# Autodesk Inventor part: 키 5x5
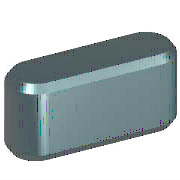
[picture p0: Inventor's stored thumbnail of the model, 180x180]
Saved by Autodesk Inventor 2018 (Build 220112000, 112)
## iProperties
IsCustomPart: 1
Created: 2012-02
Part Number: 키 5x5
Material: 강철, 연강
Description: 키 및 해당 키홈
Document SubType Name: Modeling
Standard: KS B 1311
Designer: mduedu
Standards Organization: KS
Language: ko-KR
Size Designation: 5 x 5 x 12
Categories: <MemberInstance><Categories><Category DisplayName="샤프트 부품" InternalName="7f7aeb1f-a693-4053-b835-cee3144e0d98" Mnemonic="SHFT"><Category DisplayName="키" Interna
Density: 1 g/cm^3
Appearance: 노란색
Author: mduedu
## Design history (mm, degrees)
workplane "Work Plane1"
workplane "Work Plane2"
sketch "스케치1"
  geometry: L1 (2.5, 2.5)-(9.5, 2.5); L2 (9.5, -2.5)-(2.5, -2.5); L3 (0, 9.4)-(0, -7.4) reference; L4 (-5, 0)-(30, 0) reference; L5 (12, 0)-(12, 7); A1 r 2.5 centre (2.5, 0) between (2.5, 2.5) and (2.5, -2.5); A2 r 2.5 centre (9.5, 0) between (9.5, -2.5) and (9.5, 2.5)
  constraints: 6 end point, 5 point on circle, 4 tangent, 3 point on line, 2 centre point, 1 horizontal, 1 parallel, 1 perpendicular
  dimensions: "d0" = 2.5 radius of A1 (= 0.5 x PB); "d13" = 2.5 radius of A2 (= 0.5 x PB); "d14" = 12 distance between parallel lines of L5 L3 (= NLG)
extrude "본체1" new body sketch "스케치1" taper "d3" = 0 deg; stored distance "d4" = 10
workplane "Work Plane3"
body "Solid1"
chamfer "모따기1" distance "d8" = 0.4 (= PHH); stored, may be unused: second distance "d9" = 0.4 (= PHH), angle "d15" = 45 deg
other parameters: "d1" = -3 (= -PNT), "d2" = 2 (= PH - PNT), "NLG" = 12 [user parameter; used in 3 equation terms], "PB" = 5 [user parameter; used in 2 equation terms], "PNT" = 3 [user parameter; used in 2 equation terms], "PH" = 5 [user parameter; used in 1 equation term], "PHH" = 0.4 [user parameter; used in 2 equation terms], "d10" = 0, "d16" = 0, "d17" = 0, "d18" = 0, "WDMIN" = 12 [user parameter], "PLB2" = 12 (= NLG) [user parameter], "WDMAX" = 17 [user parameter], "PLB1" = 12 (= NLG) [user parameter], "RR" = 0.16 [user parameter], "PUEB" = 2.3 [user parameter]
